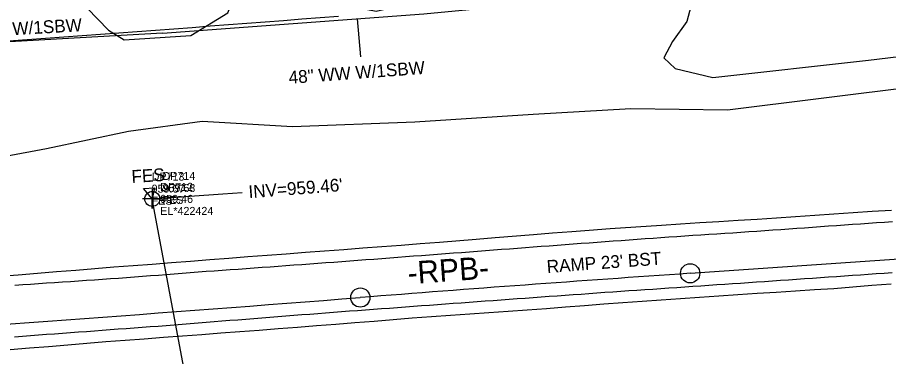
# Model space of a CAD drawing. Extents: x 1182322 to 1186765, y 572295 to 575411.
# Drawn here: x 1184083.8 to 1184355.7, y 574332.1 to 574437.9 of the extents above; entities that cross this region are included whole.
import ezdxf

# ---------------------------------------------------------------- set-up
doc = ezdxf.new("R2010")
doc.units = 0
for name, color, linetype in [('COGO Default Chain', 7, 'Continuous'), ('Default Symbol Cogo Comment', 7, 'Continuous'), ('Default Symbol Cogo Elevation', 7, 'Continuous'), ('Default Symbol Cogo Number', 7, 'Continuous'), ('Exist Horizontal Alignment', 7, 'Continuous'), ('Exist Horizontal Alignment Direction Label', 7, 'Continuous'), ('Exist Horizontal Alignment Point', 7, 'Continuous'), ('Exist Other Culture Fence Line', 7, 'Continuous'), ('Exist Other Culture Fence Line Leader', 7, 'Continuous'), ('Exist Other Culture Fence Line Text', 7, 'Continuous'), ('Exist Right of Way Line', 7, 'Continuous'), ('Exist Roads EOP', 7, 'Continuous'), ('Exist Roads EOP Other', 7, 'Continuous'), ('Exist Roads EOP Other Text', 7, 'Continuous'), ('Exist Roads EOP Text', 7, 'Continuous'), ('Exist Roads EOT', 7, 'Continuous'), ('Exist Structure Minor Pipes RCP 24 Inch', 7, 'Continuous'), ('Exist Structure Minor Pipes RCP 24 Inch Cogo Comment', 7, 'Continuous'), ('Exist Structure Minor Pipes RCP 24 Inch Cogo Elevation', 7, 'Continuous'), ('Exist Structure Minor Pipes RCP 24 Inch Cogo Number', 7, 'Continuous'), ('Exist Structure Minor Pipes RCP 24 Inch Cogo Point CELL', 7, 'Continuous'), ('Exist Structure Minor Pipes RCP 24 Inch Invert', 7, 'Continuous'), ('Exist Vegetation Woods Line', 7, 'Continuous')]:
    doc.layers.add(name, color=color, linetype=linetype)

msp = doc.modelspace()

# ---------------------------------------------------------------- linework, layer by layer
at = {"layer": 'COGO Default Chain'}
msp.add_line((1184293.8, 574358.09), (1184784.76, 574391.88), dxfattribs=at)
for centre, radius, start, end in [((1185071.5, 563056.6), 11328.22, 93.936527, 94.458763), ((1182785.88, 592367.85), 18072.01, 273.874608, 274.458763)]:
    msp.add_arc(centre, radius, start, end, dxfattribs=at)
at = {"layer": 'Exist Horizontal Alignment'}
msp.add_line((1184293.8, 574358.09), (1184784.76, 574391.88), dxfattribs=at)
for centre, radius, start, end in [((1185071.5, 563056.6), 11328.22, 93.936527, 94.458763), ((1182785.88, 592367.85), 18072.01, 273.874608, 274.458763)]:
    msp.add_arc(centre, radius, start, end, dxfattribs=at)
at = {"layer": 'Exist Horizontal Alignment Point'}
for centre in [(1184293.8, 574358.09), (1184190.83, 574350.53)]:
    msp.add_circle(centre, 3, dxfattribs=at)
at = {"layer": 'Exist Other Culture Fence Line'}
for points in [[(1184129.02, 574432.99), (1184210.64, 574439), (1184240.12, 574441.8)], [(1184129.02, 574432.99), (1183969.21, 574423.88), (1183900.3, 574421.99), (1183875.68, 574420.93), (1183770.89, 574427.81)]]:
    msp.add_lwpolyline(points, dxfattribs=at)
at = {"layer": 'Exist Other Culture Fence Line Leader'}
msp.add_line((1184189.89, 574437.47), (1184190.91, 574425.58), dxfattribs=at)
at = {"layer": 'Exist Right of Way Line'}
for centre, radius, start, end in [((1182785.88, 592367.85), 17984.01, 273.874608, 274.458763), ((1184007.06, 574337.15), 88, 93.8746, 93.8746)]:
    msp.add_arc(centre, radius, start, end, dxfattribs=at)
at = {"layer": 'Exist Roads EOP'}
for points in [[(1184078.07, 574357.16), (1184084.04, 574357.63), (1184090.02, 574358.12), (1184095.99, 574358.61), (1184101.96, 574359.11), (1184107.94, 574359.6), (1184113.92, 574360.07), (1184119.89, 574360.52), (1184125.87, 574360.98), (1184131.85, 574361.43), (1184137.82, 574361.88), (1184143.8, 574362.35), (1184149.78, 574362.82), (1184155.75, 574363.28), (1184161.73, 574363.75), (1184167.71, 574364.2), (1184173.68, 574364.65), (1184179.66, 574365.1), (1184185.64, 574365.55), (1184191.61, 574366), (1184197.59, 574366.45), (1184203.57, 574366.9), (1184209.55, 574367.35), (1184215.52, 574367.8), (1184226.99, 574368.74), (1184232.94, 574369.22), (1184244.89, 574370.2), (1184250.86, 574370.69), (1184256.84, 574371.14), (1184262.29, 574371.51), (1184268.8, 574372.01), (1184284.83, 574373.11), (1184290.81, 574373.52), (1184296.79, 574373.91), (1184302.77, 574374.29), (1184308.75, 574374.66), (1184314.74, 574375.02), (1184320.72, 574375.39), (1184326.7, 574375.79), (1184332.68, 574376.2), (1184338.66, 574376.61), (1184344.64, 574377.03), (1184350.62, 574377.42), (1184356.61, 574377.8)], [(1184356.52, 574354.74), (1184350.55, 574354.26), (1184344.57, 574353.78), (1184338.6, 574353.3), (1184332.62, 574352.91), (1184326.64, 574352.53), (1184320.65, 574352.15), (1184314.67, 574351.77), (1184308.69, 574351.35), (1184302.71, 574350.93), (1184296.73, 574350.52), (1184290.75, 574350.11), (1184284.77, 574349.72), (1184278.79, 574349.32), (1184272.81, 574348.92), (1184266.83, 574348.44), (1184260.85, 574347.96), (1184254.88, 574347.49), (1184248.9, 574347.06), (1184242.92, 574346.64), (1184236.94, 574346.22), (1184230.96, 574345.8), (1184224.98, 574345.38), (1184219, 574344.96), (1184213.02, 574344.54), (1184207.05, 574344.08), (1184201.07, 574343.6), (1184195.1, 574343.11), (1184189.12, 574342.62), (1184183.14, 574342.14), (1184177.17, 574341.68), (1184171.19, 574341.21), (1184165.22, 574340.75), (1184159.24, 574340.29), (1184153.26, 574339.83), (1184147.28, 574339.38), (1184141.31, 574338.93), (1184135.33, 574338.49), (1184129.35, 574338.04), (1184123.37, 574337.61), (1184117.4, 574337.17), (1184111.42, 574336.74), (1184105.44, 574336.25), (1184099.47, 574335.74), (1184093.5, 574335.22), (1184087.52, 574334.74), (1184081.55, 574334.27)]]:
    msp.add_lwpolyline(points, dxfattribs=at)
at = {"layer": 'Exist Roads EOP Other'}
msp.add_lwpolyline([(1184125.87, 574381.29), (1184123.18, 574384.48), (1184126.57, 574384.69)], close=True, dxfattribs=at)
at = {"layer": 'Exist Roads EOT'}
for points in [[(1184082.93, 574354.37), (1184085.42, 574354.55), (1184087.91, 574354.73), (1184090.4, 574354.9), (1184092.89, 574355.07), (1184095.38, 574355.24), (1184097.87, 574355.41), (1184100.37, 574355.58), (1184102.86, 574355.75), (1184105.35, 574355.92), (1184107.84, 574356.09), (1184110.33, 574356.26), (1184112.83, 574356.44), (1184115.32, 574356.62), (1184117.81, 574356.81), (1184120.3, 574356.99), (1184122.79, 574357.18), (1184125.28, 574357.37), (1184127.77, 574357.56), (1184130.26, 574357.75), (1184132.75, 574357.95), (1184135.24, 574358.15), (1184137.73, 574358.34), (1184140.22, 574358.54), (1184142.71, 574358.72), (1184145.2, 574358.89), (1184147.69, 574359.07), (1184150.18, 574359.25), (1184152.68, 574359.43), (1184155.17, 574359.61), (1184157.66, 574359.79), (1184160.15, 574359.97), (1184162.64, 574360.15), (1184165.13, 574360.33), (1184167.62, 574360.52), (1184170.11, 574360.7), (1184172.6, 574360.88), (1184175.09, 574361.06), (1184177.59, 574361.24), (1184180.08, 574361.42), (1184182.57, 574361.6), (1184185.06, 574361.79), (1184187.55, 574361.97), (1184190.04, 574362.16), (1184192.53, 574362.35), (1184195.02, 574362.54), (1184197.51, 574362.73), (1184200, 574362.92), (1184202.49, 574363.11), (1184204.98, 574363.3), (1184207.47, 574363.49), (1184209.96, 574363.68), (1184212.45, 574363.87), (1184214.94, 574364.06), (1184217.44, 574364.25), (1184219.93, 574364.43), (1184222.42, 574364.62), (1184224.91, 574364.81), (1184227.4, 574365), (1184229.89, 574365.19), (1184232.38, 574365.38), (1184234.87, 574365.57), (1184237.36, 574365.76), (1184239.85, 574365.95), (1184242.34, 574366.14), (1184244.83, 574366.33), (1184247.32, 574366.51), (1184249.81, 574366.7), (1184252.3, 574366.89), (1184254.79, 574367.07), (1184257.29, 574367.25), (1184259.78, 574367.44), (1184262.27, 574367.62), (1184264.76, 574367.81), (1184267.25, 574368), (1184269.74, 574368.18), (1184272.23, 574368.36), (1184274.72, 574368.54), (1184277.21, 574368.72), (1184279.7, 574368.9), (1184282.2, 574369.07), (1184284.69, 574369.25), (1184287.18, 574369.43), (1184289.67, 574369.6), (1184292.16, 574369.77), (1184294.65, 574369.93), (1184297.15, 574370.1), (1184299.64, 574370.26), (1184302.13, 574370.43), (1184304.62, 574370.59), (1184307.12, 574370.76), (1184309.61, 574370.92), (1184312.1, 574371.1), (1184314.59, 574371.27), (1184317.08, 574371.44), (1184319.57, 574371.61), (1184322.07, 574371.79), (1184324.56, 574371.97), (1184327.05, 574372.14), (1184329.54, 574372.32), (1184332.03, 574372.5), (1184334.52, 574372.68), (1184337.01, 574372.85), (1184339.51, 574373.03), (1184342, 574373.2), (1184344.49, 574373.38), (1184346.98, 574373.55), (1184349.47, 574373.72), (1184351.96, 574373.89), (1184354.46, 574374.06), (1184356.95, 574374.23)], [(1184356.9, 574358.22), (1184354.4, 574358.05), (1184351.91, 574357.88), (1184349.42, 574357.71), (1184346.93, 574357.53), (1184344.44, 574357.36), (1184341.95, 574357.19), (1184339.45, 574357.02), (1184336.96, 574356.84), (1184334.47, 574356.67), (1184331.98, 574356.5), (1184329.49, 574356.33), (1184327, 574356.15), (1184324.5, 574355.98), (1184322.01, 574355.81), (1184319.52, 574355.64), (1184317.03, 574355.46), (1184314.54, 574355.29), (1184312.05, 574355.12), (1184309.55, 574354.95), (1184307.06, 574354.78), (1184304.57, 574354.61), (1184302.08, 574354.45), (1184299.59, 574354.28), (1184297.1, 574354.11), (1184294.6, 574353.94), (1184292.11, 574353.77), (1184289.62, 574353.6), (1184287.13, 574353.43), (1184284.63, 574353.26), (1184282.14, 574353.09), (1184279.65, 574352.92), (1184277.16, 574352.75), (1184274.67, 574352.58), (1184272.17, 574352.41), (1184269.68, 574352.24), (1184267.19, 574352.07), (1184264.7, 574351.89), (1184262.21, 574351.71), (1184259.72, 574351.53), (1184257.23, 574351.35), (1184254.73, 574351.17), (1184252.24, 574350.99), (1184249.75, 574350.81), (1184247.26, 574350.64), (1184244.77, 574350.46), (1184242.28, 574350.28), (1184239.79, 574350.1), (1184237.3, 574349.92), (1184234.81, 574349.74), (1184232.31, 574349.56), (1184229.82, 574349.37), (1184227.33, 574349.19), (1184224.84, 574349.01), (1184222.35, 574348.83), (1184219.86, 574348.65), (1184217.37, 574348.47), (1184214.88, 574348.28), (1184212.39, 574348.1), (1184209.9, 574347.91), (1184207.4, 574347.73), (1184204.91, 574347.54), (1184202.42, 574347.36), (1184199.93, 574347.17), (1184197.44, 574346.99), (1184194.95, 574346.81), (1184192.46, 574346.62), (1184189.97, 574346.44), (1184187.48, 574346.25), (1184184.99, 574346.07), (1184182.49, 574345.87), (1184180, 574345.68), (1184177.51, 574345.49), (1184175.02, 574345.29), (1184172.53, 574345.1), (1184170.04, 574344.9), (1184167.55, 574344.71), (1184165.06, 574344.51), (1184162.57, 574344.32), (1184160.08, 574344.12), (1184157.59, 574343.92), (1184155.11, 574343.72), (1184152.62, 574343.53), (1184150.13, 574343.33), (1184147.64, 574343.13), (1184145.15, 574342.93), (1184142.66, 574342.74), (1184140.17, 574342.54), (1184137.68, 574342.34), (1184135.19, 574342.15), (1184132.7, 574341.95), (1184130.21, 574341.75), (1184127.72, 574341.56), (1184125.23, 574341.37), (1184122.74, 574341.19), (1184120.25, 574341), (1184117.75, 574340.82), (1184115.26, 574340.63), (1184112.77, 574340.45), (1184110.28, 574340.26), (1184107.79, 574340.08), (1184105.3, 574339.89), (1184102.81, 574339.71), (1184100.32, 574339.52), (1184097.83, 574339.34), (1184095.34, 574339.15), (1184092.85, 574338.97), (1184090.36, 574338.78), (1184087.87, 574338.6), (1184085.38, 574338.41), (1184082.88, 574338.23)]]:
    msp.add_lwpolyline(points, dxfattribs=at)
at = {"layer": 'Exist Structure Minor Pipes RCP 24 Inch'}
msp.add_line((1184152.17, 574240.64), (1184125.87, 574381.29), dxfattribs=at)
at = {"layer": 'Exist Structure Minor Pipes RCP 24 Inch Cogo Point CELL'}
msp.add_lwpolyline([(1184125.87, 574384.29), (1184125.87, 574378.29), (1184125.87, 574381.29), (1184128.87, 574381.29), (1184122.87, 574381.29)], dxfattribs=at)
msp.add_circle((1184125.87, 574381.29), 2.34, dxfattribs=at)
at = {"layer": 'Exist Structure Minor Pipes RCP 24 Inch Invert'}
msp.add_lwpolyline([(1184125.87, 574381.29), (1184147.94, 574382.86), (1184153.92, 574383.32)], dxfattribs=at)
at = {"layer": 'Exist Vegetation Woods Line'}
for points in [[(1184571.69, 574471.81), (1184537.5, 574460.83), (1184495.76, 574442.25), (1184471.16, 574448.83), (1184434.87, 574440.81), (1184423.84, 574428.9), (1184417.92, 574420.26), (1184364.78, 574416.37), (1184305.45, 574408.99), (1184275.3, 574409.38), (1184244.77, 574407.57)], [(1184077.72, 574438.41), (1184084.35, 574447.66), (1184084.57, 574454.47), (1184086.61, 574459.35), (1184091.91, 574459.79), (1184097.87, 574455.16), (1184105.52, 574440.79), (1184112.18, 574433.93), (1184117.09, 574430.87), (1184137.92, 574432.28), (1184149.43, 574439.31), (1184152.13, 574446.1), (1184154.11, 574453.09), (1184156.65, 574457.8), (1184158.64, 574460.52), (1184167.87, 574455.23), (1184186.54, 574441.61), (1184195.76, 574439.77), (1184206.85, 574442.27)], [(1184206.85, 574442.27), (1184237.29, 574448.02), (1184261.24, 574444.22), (1184282.76, 574449.21), (1184291.09, 574453.75), (1184296.48, 574450.68), (1184292.76, 574436.62), (1184288.28, 574430.36), (1184285.57, 574425.22), (1184289.15, 574421.98), (1184300.89, 574419.17), (1184349.48, 574424.51), (1184395, 574430.02)], [(1184244.77, 574407.57), (1184207.89, 574405.25), (1184169.63, 574403.78), (1184141.45, 574405.41), (1184118.5, 574402.28), (1184092.9, 574396.93), (1184080.08, 574394.54)]]:
    msp.add_lwpolyline(points, dxfattribs=at)

# ---------------------------------------------------------------- texts
at = {"layer": 'Default Symbol Cogo Comment'}
for p in [(1184125.68, 574379.48), (1184129.07, 574379.69)]:
    msp.add_text('FES', height=2.5, dxfattribs=at).set_placement(p)
at = {"layer": 'Default Symbol Cogo Elevation'}
for s, p in [('959.67', (1184125.68, 574383.23)), ('959.68', (1184129.07, 574383.44))]:
    msp.add_text(s, height=2.5, dxfattribs=at).set_placement(p)
at = {"layer": 'Default Symbol Cogo Number'}
for s, p in [('DP713', (1184125.68, 574386.98)), ('DP714', (1184129.07, 574387.19))]:
    msp.add_text(s, height=2.5, dxfattribs=at).set_placement(p)
at = {"layer": 'Exist Horizontal Alignment Direction Label'}
msp.add_text('-RPB-', height=7, rotation=4.0975, dxfattribs=at).set_placement((1184205.8, 574354.67))
at = {"layer": 'Exist Other Culture Fence Line Text'}
for rotation, p in [(3.2605, (1184061.44, 574431.14)), (4.2166, (1184168.59, 574417.14))]:
    msp.add_text('48" WW W/1SBW', height=4, rotation=rotation, dxfattribs=at).set_placement(p)
at = {"layer": 'Exist Roads EOP Other Text'}
msp.add_text('FES', height=4, rotation=3.575, dxfattribs=at).set_placement((1184119.5, 574386.25))
at = {"layer": 'Exist Roads EOP Text'}
msp.add_text("RAMP 23' BST", height=4, rotation=4.2839, dxfattribs=at).set_placement((1184249.17, 574358.16))
at = {"layer": 'Exist Structure Minor Pipes RCP 24 Inch Cogo Comment'}
msp.add_text('EL*422424', height=2.5, dxfattribs=at).set_placement((1184128.37, 574376.29))
at = {"layer": 'Exist Structure Minor Pipes RCP 24 Inch Cogo Elevation'}
msp.add_text('959.46', height=2.5, dxfattribs=at).set_placement((1184128.37, 574380.04))
at = {"layer": 'Exist Structure Minor Pipes RCP 24 Inch Cogo Number'}
msp.add_text('DP712', height=2.5, dxfattribs=at).set_placement((1184128.37, 574383.79))
at = {"layer": 'Exist Structure Minor Pipes RCP 24 Inch Invert'}
msp.add_text("INV=959.46'", height=4, rotation=4.4018, dxfattribs=at).set_placement((1184156.07, 574381.48))

doc.saveas('drawing.dxf')
